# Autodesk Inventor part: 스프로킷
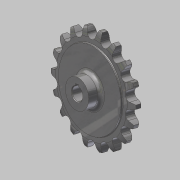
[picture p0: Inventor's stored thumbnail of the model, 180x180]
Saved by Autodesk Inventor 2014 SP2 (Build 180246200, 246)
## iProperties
Created: 2016-03
Part Number: 스프로킷
Material: 강철, 탄소
Document SubType Name: Modeling
Designer: mduedu
Density: 7.87 g/cm^3
Mass: 301.857 g
Surface Area: 120.622 cm^2
Volume: 38.3554 cm^3
Appearance: 반광택
Author: mduedu
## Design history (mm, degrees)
sketch "스케치1"
  geometry: L1 (0, 5)-(29.5, 5); L2 (29.5, 5)-(29.5, 4.1); L3 (30, 3.6)-(33.625, 3.6); L4 (40, 2)-(40, 0); L5 (40, 0)-(0, 0); L6 (0, 0)-(0, 5); L7 (0, -5)-(29.5, -5); L8 (29.5, -5)-(29.5, -4.1); L9 (30, -3.6)-(33.625, -3.6); L10 (40, -2)-(40, 0); L11 (0, 0)-(0, -5); A1 r 13.5 centre (33.625, -9.9) between (40, 2) and (33.625, 3.6); A2 r 13.5 centre (33.625, 9.9) between (33.625, -3.6) and (40, -2); A3 r 0.5 centre (30, 4.1) between (29.5, 4.1) and (30, 3.6); A4 r 0.5 centre (30, -4.1) between (30, -3.6) and (29.5, -4.1); 2 further points
  constraints: 22 end point, 8 point on circle, 6 symmetric about line, 5 tangent, 4 centre point, 4 parallel, 4 point on line, 1 equal radius, 1 horizontal, 1 perpendicular, 1 other
  dimensions: "d0" = 80 diameter of L4 L6; "d2" = 59 diameter of L2 L6; "d3" = 1.6 vertical distance of L4.start L3.end; "d4" = 3.6 distance from line of L4.end L3; "d5" = 5 distance between parallel lines of L5 L1; "d6" = 13.5 radius of A1; "d15" = 0.5 radius of A3
revolve "회전1" sketch "스케치1" stored, may be unused: angle "d7" = 90 deg
sketch "스케치2" dims "d8" = 65.2, "d11" = 80
  geometry: L1 (0, 0)-(0, 32.6); A1 r 36.57 centre (0, 0) between (-16.231, 32.771) and (0, 36.57); A2 r 3.97 centre (0, 36.57) between (-3.866, 35.665) and (0, 32.6); A3 r 12.7 centre (-16.231, 32.771) between (-3.866, 35.665) and (-5.534, 39.615); A4 r 12.7 centre (16.231, 32.771) between (5.534, 39.615) and (3.866, 35.665); A5 r 3.97 centre (0, 36.57) between (0, 32.6) and (3.866, 35.665); A6 r 40 centre (0, 0) between (5.534, 39.615) and (-5.534, 39.615); 2 further points
  constraints: 12 point on circle, 6 centre point, 4 coincident, 3 symmetric about line, 2 end point, 1 point on line, 1 tangent, 1 vertical, 1 vertical alignment, 7 other
  dimensions: "d10" = 73.14 diameter of A1; "d12" = 12.7 radius of A3
extrude "돌출1" cut sketch "스케치2" stored distance "d13" = 10; taper "d14" = 0 deg
sketch "스케치3"
  geometry: C1 r 11 at (0, 0); 1 further point
  constraints: 1 centre point, 1 coincident
  dimensions: "d19" = 22 diameter of C1
extrude "돌출2" join sketch "스케치3" distance "d20" = 10; taper "d21" = 0 deg
fillet "모깎기1" dims "d22" = 3
sketch "스케치4"
  geometry: L1 (-1.5, 0)-(1.5, 0); L2 (1.5, 0)-(1.5, 6.4); L3 (1.5, 6.4)-(-1.5, 6.4); L4 (-1.5, 6.4)-(-1.5, 0); C1 r 5 at (0, 0); 2 further points
  constraints: 8 end point, 2 coincident, 2 parallel, 1 centre point, 1 horizontal, 1 midpoint, 1 perpendicular
  dimensions: "d23" = 10 diameter of C1; "d25" = 3 distance of L2.end L3.end; "d26" = 6.4 distance of L1.end L2.end
extrude "돌출3" cut sketch "스케치4" stored distance "d27" = 8; taper "d28" = 0 deg
chamfer "모따기1" distance "d29" = 0.5; stored, may be unused: second distance "d30" = 2, angle "d31" = 45 deg
sketch "스케치5" dims "d33" = 50
  geometry: C1 r 1 at (0, 25); 2 further points
  constraints: 2 vertical alignment, 1 centre point, 1 coincident, 2 other
  dimensions: "d32" = 2 diameter of C1
extrude "돌출4" join sketch "스케치5" distance "d34" = 0.5; taper "d35" = 0 deg
node "솔리드1"
pattern_circular "원형 패턴1" dims angle "d17" = 360 deg
